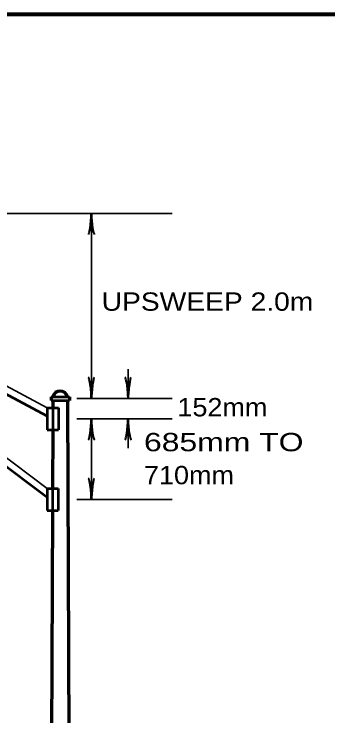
# Model space of a CAD drawing. Extents: x -32 to 824, y -12 to 532.
# Drawn here: x 355.9 to 407.2, y 410.4 to 525.2 of the extents above; entities that cross this region are included whole.
import ezdxf

# ---------------------------------------------------------------- set-up
doc = ezdxf.new("R2010")
doc.units = 0
doc.header["$LTSCALE"] = 1.2
doc.layers.add('1', color=7, linetype='Continuous', lineweight=13)

msp = doc.modelspace()

# ---------------------------------------------------------------- linework, layer by layer
at = {"layer": '1', "lineweight": 35}
for p, q in [((293.35, 492.621), (381.702, 492.621)), ((368.502, 462.321), (368.502, 492.621)), ((361.244, 447.621), (315.243, 482.285)), ((361.297, 460.821), (318.916, 483.355)), ((374.502, 462.321), (374.502, 467.121)), ((366.102, 462.321), (381.702, 462.321)), ((366.102, 459.021), (381.702, 459.021)), ((368.502, 445.821), (368.502, 459.021)), ((374.502, 454.221), (374.502, 459.021)), ((366.102, 445.821), (381.702, 445.821))]:
    msp.add_line(p, q, dxfattribs=at)
at = {"layer": '1', "lineweight": 53}
for p, q in [((361.297, 459.461), (318.353, 482.296)), ((361.244, 446.118), (314.521, 481.327)), ((361.902, 462.621), (364.902, 462.621)), ((361.902, 462.021), (364.902, 462.021)), ((361.297, 460.821), (363.097, 460.821)), ((361.297, 460.821), (361.297, 457.221)), ((362.197, 460.821), (362.183, 457.221)), ((363.097, 460.821), (363.097, 457.221)), ((361.297, 457.221), (363.097, 457.221)), ((361.244, 447.621), (363.044, 447.621)), ((361.244, 447.621), (361.244, 444.021)), ((362.144, 447.621), (362.13, 444.021)), ((363.044, 447.621), (363.044, 444.021)), ((361.244, 444.021), (363.044, 444.021))]:
    msp.add_line(p, q, dxfattribs=at)
at = {"layer": '1', "lineweight": 70}
for p, q in [((361.902, 462.621), (361.902, 462.021)), ((362.202, 462.021), (362.197, 460.821)), ((364.602, 462.021), (365.202, 313.221)), ((364.902, 462.621), (364.902, 462.021)), ((362.183, 457.221), (362.144, 447.621)), ((362.13, 444.021), (361.602, 313.221))]:
    msp.add_line(p, q, dxfattribs=at)
at = {"layer": '1', "lineweight": 158}
msp.add_lwpolyline([(817.469, 525.227), (25.769, 525.127), (25.869, -0.873)], dxfattribs=at)
at = {"layer": '1', "lineweight": 70}
msp.add_arc((363.402, 462.325), 1.234, 13.87704, 166.12296, dxfattribs=at)
at = {"layer": '1', "lineweight": 40}
for centre, major_axis, ratio, start_param, end_param in [((368.248, 491.276), (0.211, 2.108), 0.07063, 3.1407148, 5.41811), ((368.248, 491.276), (0.211, 2.108), 0.07063, 3.1407148, 5.41811), ((368.834, 491.311), (-0.187, 2.143), 0.122415, 0.8963533, 3.1415927), ((368.834, 491.311), (-0.187, 2.143), 0.122415, 0.8963533, 3.1415927), ((368.171, 463.63), (0.187, -2.143), 0.122415, 0.8963533, 3.1415927), ((368.171, 463.63), (0.187, -2.143), 0.122415, 0.8963533, 3.1415927), ((368.756, 463.665), (-0.211, -2.108), 0.07063, 3.1407148, 5.41811), ((368.756, 463.665), (-0.211, -2.108), 0.07063, 3.1407148, 5.41811), ((374.171, 463.63), (0.187, -2.143), 0.122415, 0.8963533, 3.1415927), ((374.171, 463.63), (0.187, -2.143), 0.122415, 0.8963533, 3.1415927), ((374.756, 463.665), (-0.211, -2.108), 0.07063, 3.1407148, 5.41811), ((374.756, 463.665), (-0.211, -2.108), 0.07063, 3.1407148, 5.41811), ((368.248, 457.676), (0.211, 2.108), 0.07063, 3.1407148, 5.41811), ((368.248, 457.676), (0.211, 2.108), 0.07063, 3.1407148, 5.41811), ((368.834, 457.711), (-0.187, 2.143), 0.122415, 0.8963533, 3.1415927), ((368.834, 457.711), (-0.187, 2.143), 0.122415, 0.8963533, 3.1415927), ((374.248, 457.676), (0.211, 2.108), 0.07063, 3.1407148, 5.41811), ((374.248, 457.676), (0.211, 2.108), 0.07063, 3.1407148, 5.41811), ((374.834, 457.711), (-0.187, 2.143), 0.122415, 0.8963533, 3.1415927), ((374.834, 457.711), (-0.187, 2.143), 0.122415, 0.8963533, 3.1415927), ((368.171, 447.13), (0.187, -2.143), 0.122415, 0.8963533, 3.1415927), ((368.171, 447.13), (0.187, -2.143), 0.122415, 0.8963533, 3.1415927), ((368.756, 447.165), (-0.211, -2.108), 0.07063, 3.1407148, 5.41811), ((368.756, 447.165), (-0.211, -2.108), 0.07063, 3.1407148, 5.41811)]:
    msp.add_ellipse(centre, major_axis=major_axis, ratio=ratio, start_param=start_param, end_param=end_param, dxfattribs=at)

# ---------------------------------------------------------------- texts
at = {"layer": '1'}
for s, width, p in [('UPSWEEP 2.0m', 1.15, (370.18, 476.688)), ('152mm', 1.1, (382.569, 459.411)), ('685mm TO', 1.3, (377.104, 453.705)), ('710mm', 1.1, (377.104, 448.305))]:
    msp.add_text(s, height=3, dxfattribs=dict(at, width=width)).set_placement(p)

doc.saveas('drawing.dxf')
